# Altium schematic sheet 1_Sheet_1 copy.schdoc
size 302 x 215 mm; Name: A_A4; Symbol: A_A4; Device: A_A4; @Project Name: Quectel_EC200U_Board; REV: 1.1; Date: 11-07-24; Sheet: 1/1; Draw By: Anusha; Company: FervidSmart Solutions; Convert to PCB: yes; Add into BOM: yes; @Page No: 1; @Page Count: 3; @Schematic Name: Quectel_EC200U with BuckBoost Board; @Board Name: Quectel_EC200U with BuckBoost Board; @Update Date: 2025-06-23; @Create Time: 12:09:23; @Update Time: 16:58:45; @Page Name: Sheet_1 copy; @Create Date: 2025-06-19
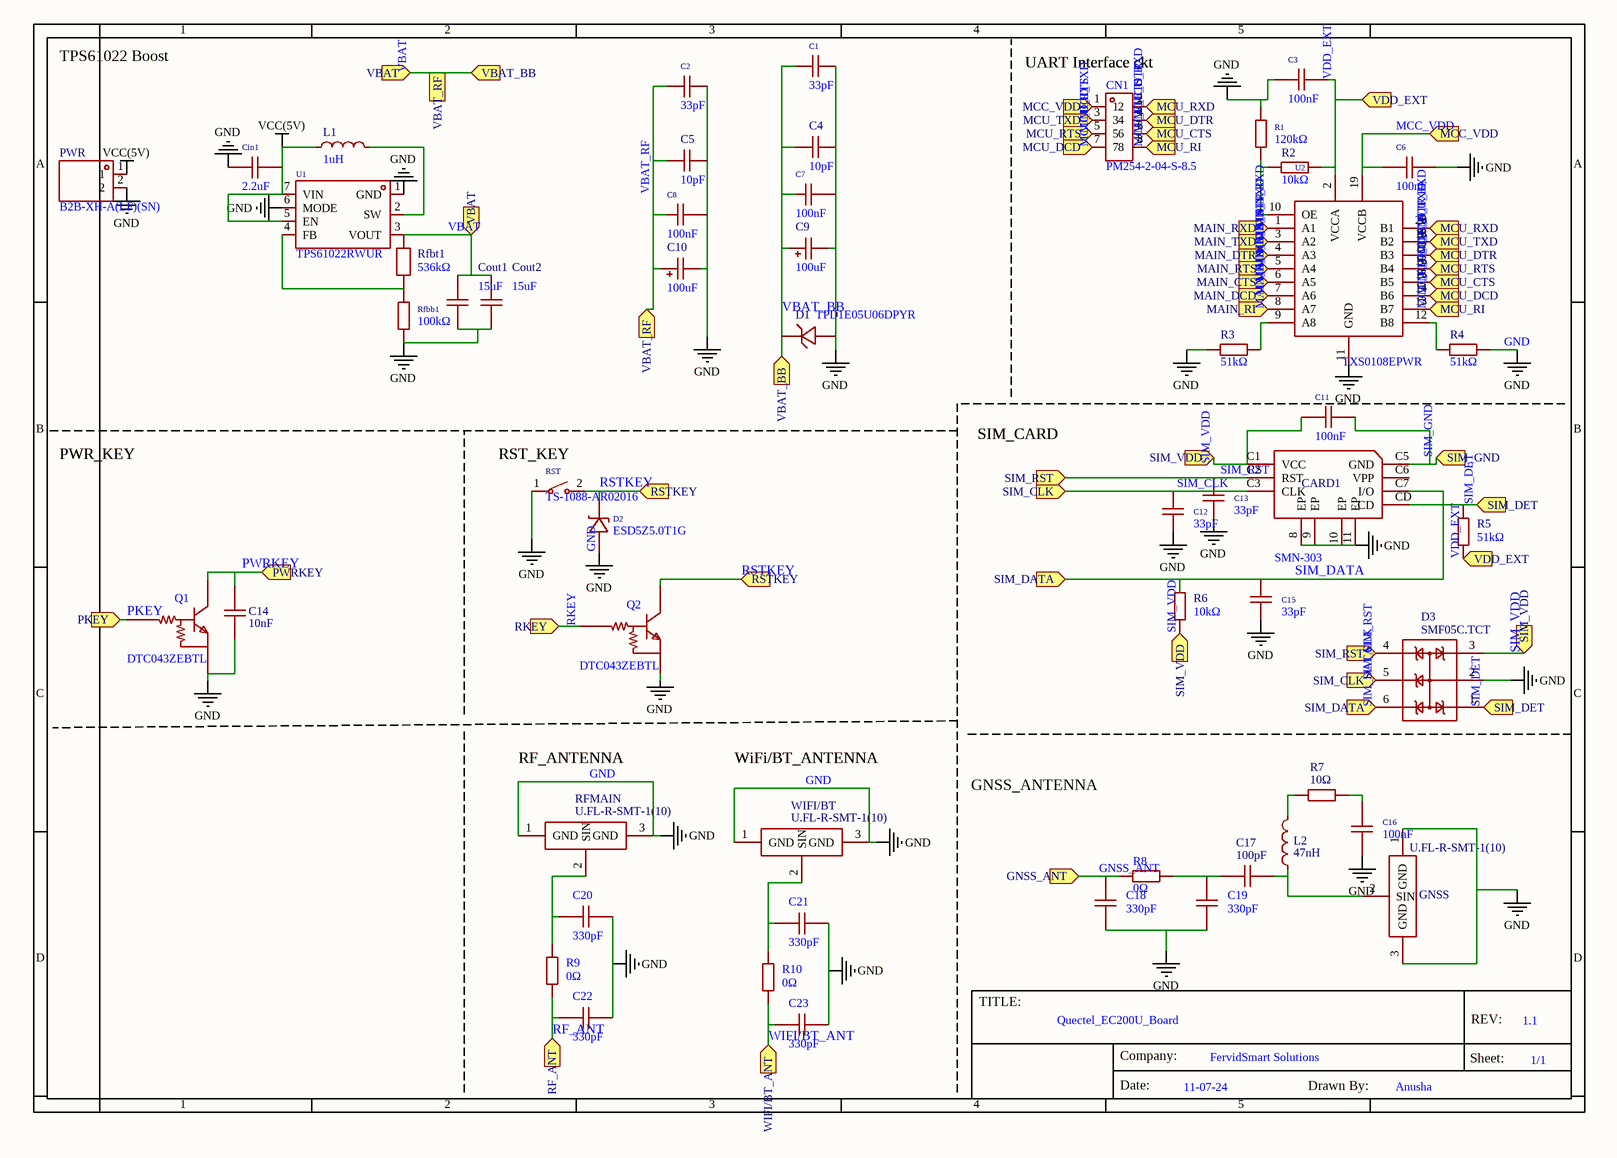
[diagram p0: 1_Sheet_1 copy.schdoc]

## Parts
C1  33pF  [C0402]
C2  33pF  [C0402]
C3  100nF  [C0402]
C4  10pF  [C0402]
C5  10pF  [C0402]
C6  100nF  [C0402]
C7  100nF  [C0402]
C8  100nF  [C0402]
C9  100uF  [CASE-B_3528]
C10  100uF  [CASE-B_3528]
C11  100nF  [C0402]
C12  33pF  [C0402]
C13  33pF  [C0402]
C14  10nF  [C0603]
C15  33pF  [C0402]
C16  100nF  [C0402]
C17  100pF  [C0603]
C18  330pF  [C0402]
C19  330pF  [C0402]
C20  330pF  [C0402]
C21  330pF  [C0402]
C22  330pF  [C0402]
C23  330pF  [C0402]
CARD1  SMN-303  [SIM-SMD_SMN-303]
Cin1  2.2uF  [C0603]
CN1  PM254-2-04-S-8.5  [HDR-SMD_8P-P2.54-V-F-R2-C4-S7.1]
Cout1  15uF  [C1812]
Cout2  15uF  [C1812]
D1  TPD1E05U06DPYR  [X2SON-2_L1.0-W0.6-P0.70-RD]
D2  ESD5Z5.0T1G  [SOD-523F_L1.2-W0.8-LS1.7-RD]
D3  SMF05C.TCT  [SC-70-6_L2.2-W1.3-P0.65-LS2.1-BR]
GNSS  U.FL-R-SMT-1(10)  [ANT-SMD_UFL-R-SMT-1-10]
L1  1uH  [IND-SMD_L4.0-W4.0_XFL4020-102MEB]
L2  47nH  [IND-SMD_L1.6-W0.8-1]
PWR  B2B-XH-A(LF)(SN)  [CONN-TH_B2B-XH-A-LF-SN]
Q1  DTC043ZEBTL  [SOT-416_L1.6-W0.8-P1.00-LS1.6-BR]
Q2  DTC043ZEBTL  [SOT-416_L1.6-W0.8-P1.00-LS1.6-BR]
R1  120kΩ  [R0402]
R2  10kΩ  [R0402]
R3  51kΩ  [R0402]
R4  51kΩ  [R0402]
R5  51kΩ  [R0402]
R6  10kΩ  [R0402]
R7  10Ω  [R0603]
R8  0Ω  [R0402]
R9  0Ω  [R0402]
R10  0Ω  [R0402]
Rfbb1  100kΩ  [R0603]
Rfbt1  536kΩ  [R0603]
RFMAIN  U.FL-R-SMT-1(10)  [ANT-SMD_UFL-R-SMT-1-10]
RST  TS-1088-AR02016  [SW-SMD_L3.9-W3.0-P4.45]
U1  TPS61022RWUR  [VQFN-7_L2.0-W2.0-P0.55-TL_RWU]
U2  TXS0108EPWR  [TSSOP-20_L6.5-W4.4-P0.65-LS6.4-BL]
WIFI/BT  U.FL-R-SMT-1(10)  [ANT-SMD_UFL-R-SMT-1-10]

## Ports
GNSS_ANT (in), MAIN_CTS (in), MAIN_DCD (in), MAIN_DTR (in), MAIN_RI (in), MAIN_RTS (in), MAIN_RXD (in), MAIN_TXD (in), MCC_VDD (in), MCU_CTS (in), MCU_DCD (in), MCU_DTR (in), MCU_RI (in), MCU_RTS (in), MCU_RXD (in), MCU_TXD (in), PKEY (in), PWRKEY (in), RF_ANT (in), RKEY (in), RSTKEY (in), SIM_CLK (in), SIM_DATA (in), SIM_DET (in), SIM_GND (in), SIM_RST (in), SIM_VDD (in), VBAT (in), VBAT_BB (in), VBAT_RF (in), VDD_EXT (in), WIFI/BT_ANT (in)

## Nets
GND: C1.2 C2.2 C3.1 C4.2 C5.2 C6.2 C7.2 C8.2 C9.2 C10.2 C12.1 C13.1 C14.1 C15.1 C16.1 C18.2 C19.2 C20.1 C21.1 C22.1 C23.1 CARD1.8(EP) CARD1.9(EP) CARD1.10(EP) CARD1.11(EP) Cin1.1 Cout1.1 Cout2.1 D1.2(GND) D2.2(A) D3.2 GNSS.1(GND) GNSS.3(GND) PWR.2 Q1.2(E) Q2.2(E) R1.2 R3.1 R4.2 Rfbb1.1 RFMAIN.1(GND) RFMAIN.3(GND) RST.1 U1.1(GND) U1.6(MODE) U2.11(GND) WIFI/BT.1(GND) WIFI/BT.3(GND)
VCC(5V): Cin1.2 L1.1 PWR.1 U1.5(EN) U1.7(VIN)
GNSS_ANT: C18.1 R8.2 ; port GNSS_ANT
MAIN_CTS: U2.6(A5) ; port MAIN_CTS
MAIN_DCD: U2.7(A6) ; port MAIN_DCD
MAIN_DTR: U2.4(A3) ; port MAIN_DTR
MAIN_RI: U2.8(A7) ; port MAIN_RI
MAIN_RTS: U2.5(A4) ; port MAIN_RTS
MAIN_RXD: U2.1(A1) ; port MAIN_RXD
MAIN_TXD: U2.3(A2) ; port MAIN_TXD
MCC_VDD: C6.1 CN1.1 U2.19(VCCB) ; port MCC_VDD
MCU_CTS: CN1.6 U2.15(B5) ; port MCU_CTS
MCU_DCD: CN1.7 U2.14(B6) ; port MCU_DCD
MCU_DTR: CN1.4 U2.17(B3) ; port MCU_DTR
MCU_RI: CN1.8 U2.13(B7) ; port MCU_RI
MCU_RTS: CN1.5 U2.16(B4) ; port MCU_RTS
MCU_RXD: CN1.2 U2.20(B1) ; port MCU_RXD
MCU_TXD: CN1.3 U2.18(B2) ; port MCU_TXD
PKEY: Q1.1(B) ; port PKEY
PWRKEY: C14.2 Q1.3(C) ; port PWRKEY
RF_ANT: C22.2 R9.1 ; port RF_ANT
RKEY: Q2.1(B) ; port RKEY
RSTKEY: D2.1(C) Q2.3(C) RST.2 ; port RSTKEY
SIM_CLK: C12.2 CARD1.C3(CLK) D3.5 ; port SIM_CLK
SIM_DATA: C15.2 CARD1.C7(I/O) D3.6 R6.2 ; port SIM_DATA
SIM_DET: CARD1.CD D3.1 R5.2 ; port SIM_DET
SIM_GND: C11.2 CARD1.C5(GND) ; port SIM_GND
SIM_RST: C13.2 CARD1.C2(RST) D3.4 ; port SIM_RST
SIM_VDD: C11.1 CARD1.C1(VCC) D3.3 R6.1 ; port SIM_VDD
VBAT: C1.1 C2.1 C4.1 C5.1 C7.1 C8.1 C9.1 C10.1 Cout1.2 Cout2.2 D1.1(I/O) Rfbt1.2 U1.3(VOUT) ; port VBAT_BB, port VBAT, port VBAT_RF  [also labelled VBAT_BB, VBAT_RF]
VDD_EXT: C3.2 R2.2 R5.1 U2.2(VCCA) ; port VDD_EXT
WIFI/BT_ANT: C23.2 R10.1 ; port WIFI/BT_ANT
NetC16_2: C16.2 R7.1
NetC17_1: C17.1 GNSS.2(SIN) L2.1
NetC17_2: C17.2 C19.1 R8.1
NetC20_2: C20.2 R9.2 RFMAIN.2(SIN)
NetC21_2: C21.2 R10.2 WIFI/BT.2(SIN)
NetL1_2: L1.2 U1.2(SW)
NetL2_2: L2.2 R7.2
NetR1_1: R1.1 R2.1 U2.10(OE)
NetR3_2: R3.2 U2.9(A8)
NetR4_1: R4.1 U2.12(B8)
NetRfbb1_2: Rfbb1.2 Rfbt1.1 U1.4(FB)

Not connected (* = marked no-connect by the designer): CARD1 C6(VPP)

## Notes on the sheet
- TPS61022 Boost
- (near CN1) UART Interface ckt
- PWR_KEY
- (near RST) RST_KEY
- SIM_CARD
- RF_ANTENNA
- WiFi/BT_ANTENNA
- GNSS_ANTENNA

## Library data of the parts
C1 C2 C12 C13 C15 = 0402CG330J500NT: Manufacturer: FH(风华); Symbol: CC0402JRNPO9BN330; Add into BOM: yes; Tolerance: ±5%; Check: true
C3 C6-C8 C11 C16 = CL05B104KO5NNNC: Manufacturer: SAMSUNG(三星); Symbol: CC0402KRX7R7BB104; Add into BOM: yes; Tolerance: ±10%; Check: true
C4 C5 = CL05C100JB5NNNC: Manufacturer: SAMSUNG(三星); Symbol: CC0402JRNPO9BN100; Add into BOM: yes; Tolerance: ±5%; Check: true
C9 C10 = TAJB107K006RNJ: Manufacturer: Kyocera AVX; Add into BOM: yes; Tolerance: ±10%; Equivalent Series Resistance(ESR): 1.7Ω@100kHz; Check: true
C14 = 0603B103K500NT: Manufacturer: FH(风华); Add into BOM: yes; Tolerance: ±10%; Voltage Rating: 50V; Temperature Coefficient: X7R; Check: true
C17 = CL10C101JB8NNNC: Manufacturer: SAMSUNG(三星); Add into BOM: yes; Tolerance: ±5%; Check: true
C18-C23 = CC0402JRNPO9BN331: Manufacturer: YAGEO(国巨); Add into BOM: no; Convert to PCB: yes; Tolerance: ±5%; Check: true
CARD1 = SMN-303: Manufacturer: XUNPU(讯普); Add into BOM: yes; Card Connection Mode: Self-bouncing; Card Type: Nano SIM card; Connector Type: Card Slot; Card Detection: With Card Insertion Detection; Body Height (Max): 1.37mm; Check: true
Cin1 = CL10A225KO8NNNC: Manufacturer: SAMSUNG(三星); Symbol: GRM21BR71A225KA01L; Add into BOM: yes; Tolerance: ±10%; Check: true
CN1 = PM254-2-04-S-8.5: Manufacturer: HCTL(华灿天禄); Add into BOM: yes; Holes Structure: 2x4P; Pitch: 2.54mm; Circular Hole / Square Hole: 方孔; Number of Holes: 8P; Current Rating (Max): 3A; Holes Direction: Top; Soldering Temperature(Max): 260℃@5S; Check: true
Cout1 Cout2 = C4532X7R1E156MT000N: Manufacturer: TDK; Add into BOM: yes; Tolerance: ±20%; Voltage Rating: 25V; Temperature Coefficient: X7R; Check: true
D1 = TPD1E05U06DPYR: Manufacturer: TI(德州仪器); Add into BOM: yes; Reverse Stand-Off Voltage (Vrwm): 5.5V; Maximum Clamping Voltage: 14V; Peak Pulse Current (Ipp): 2.5A@8/20us; Breakdown Voltage: 6V; Type: TVS; Check: true
D2 = ESD5Z5.0T1G_C82044: Manufacturer: onsemi(安森美); Add into BOM: yes; polarity: Unidirectional; Reverse Stand-Off Voltage (Vrwm): 5V; Maximum Clamping Voltage: 18.6V; Peak Pulse Current (Ipp)@10/1000us: 9.4A; Peak Pulse Power Dissipation (Ppp)@10/1000us: 174W; Breakdown Voltage: 6.2V; Number of Lines: 单路; Type: ESD; Check: true
D3 = SMF05C.TCT: Manufacturer: SEMTECH; Convert to PCB: yes; Check: true
GNSS RFMAIN WIFI/BT = U.FL-R-SMT-1(10): Manufacturer: HRS; Convert to PCB: yes; Check: true
L1 = XFL4020-102MEC: Manufacturer: Coilcraft(线艺); Add into BOM: yes; Tolerance: ±20%; Type: Shielded Power Inductor; Check: true
L2 = LQW18AN47NJ00D: Manufacturer: MuRata; Convert to PCB: yes; Check: true
PWR = B2B-XH-A(LF)(SN): Manufacturer: JST; Add into BOM: yes; Pins Structure: 1x2P; Pitch: 2.5mm; Reference Series: XH; Number of PINs Per Row: 2; Current Rating (Max): 3A; Rated Voltage (Max): 250V; Plastic Material: PA66; Flame Retardant Rating: UL94V-0; Supplementary Features: K-leg punch; Z-Height of the Board: 7mm; X-Length of Bottom Edge on Board (Spacing Line): 7.4mm; Y-Width of Bottom Edge on Board: 5.75mm; Check: true
Q1 Q2 = DTC043ZEBTL: Manufacturer: ROHM(罗姆); Add into BOM: yes; Transistor Type: 1个NPN-预偏置; Collector-Emitter Breakdown Voltage (Vceo): 50V; Collector Current (Ic): 100mA; Power Dissipation (Pd): 150mW; DC Current Gain (hFE@Ic,Vce): 80@5mA,10V; Transition Frequency (fT): 250MHz; Collector-Emitter Saturation Voltage (VCE(sat)@Ic,Ib): 150mV@500uA,5mA; Check: true
R1 = RC0402FR-07120KL: Manufacturer: YAGEO(国巨); Add into BOM: yes; Tolerance: ±1%; Temperature Coefficient: ±100ppm/℃; Check: true
R2 R6 = 0402WGF1002TCE: Manufacturer: UNI-ROYAL(厚声); Symbol: RC0402FR-0710KL; Add into BOM: yes; Tolerance: ±1%; Temperature Coefficient: ±100ppm/℃; Check: true
R3-R5 = 0402WGF5102TCE: Manufacturer: UNI-ROYAL(厚声); Symbol: RC0402FR-0751KL; Add into BOM: yes; Tolerance: ±1%; Temperature Coefficient: ±100ppm/℃; Check: true
R7 = 0603WAF100JT5E: Manufacturer: UNI-ROYAL(厚声); Add into BOM: yes; Tolerance: ±1%; Temperature Coefficient: ±400ppm/℃; Check: true
R8-R10 = 0402WGF0000TCE: Manufacturer: UNI-ROYAL(厚声); Symbol: RC0402FR-070RL; Add into BOM: yes; Tolerance: ±1%; Temperature Coefficient: ±800ppm/℃; Check: true
Rfbb1 = 0603WAF1003T5E: Manufacturer: UNI-ROYAL(厚声); Symbol: RC0603FR-07100KL; Add into BOM: yes; Tolerance: ±1%; Temperature Coefficient: ±100ppm/℃; Check: true
Rfbt1 = FRC0603F5363TS: Manufacturer: FOJAN(富捷); Add into BOM: yes; Tolerance: ±1%; Temperature Coefficient: ±100ppm/℃; Check: true
RST = TS-1088-AR02016: Manufacturer: XUNPU(讯普); Symbol: TS-1088R-02026; Add into BOM: yes; Circuit: SPST; Actuator Style: Round Button; Operating Force: 160gf; Switch Length: 4mm; Switch Width: 3mm; Switch Height: 2mm; Strike Gundam: 不带; Contact Current: 50mA; Voltage Rating (DC): 12V; Insulation Resistance: 100MΩ; Actuator/Cap Color: Black; Pin Style: SMDSplicing; Mechanical Life: 10万次; Check: true
U1 = TPS61022RWUR: Manufacturer: TI(德州仪器); Add into BOM: yes; Function: boost converterType; Output Type: Adjustable; Input Voltage: 500mV~5.5V; Output Voltage: 2.2V~5.5V; Switching Frequency: 1MHz；600kHz; Number of Outputs: 1; Topology: Boost; Switch tube (built-in/external): 内置; Check: true
U2 = TXS0108EPWR: Manufacturer: TI(德州仪器); Add into BOM: yes; Channel Type: Bi-Directional; Data Rate: 60Mbps; Supply Voltage (VCCA): 1.4V~3.6V; Supply Voltage (VCCB): 1.65V~5.5V; Number of Circuits: 1; Channels per Circuit: 8; Output Type: Open Drain；Push-pull; Check: true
